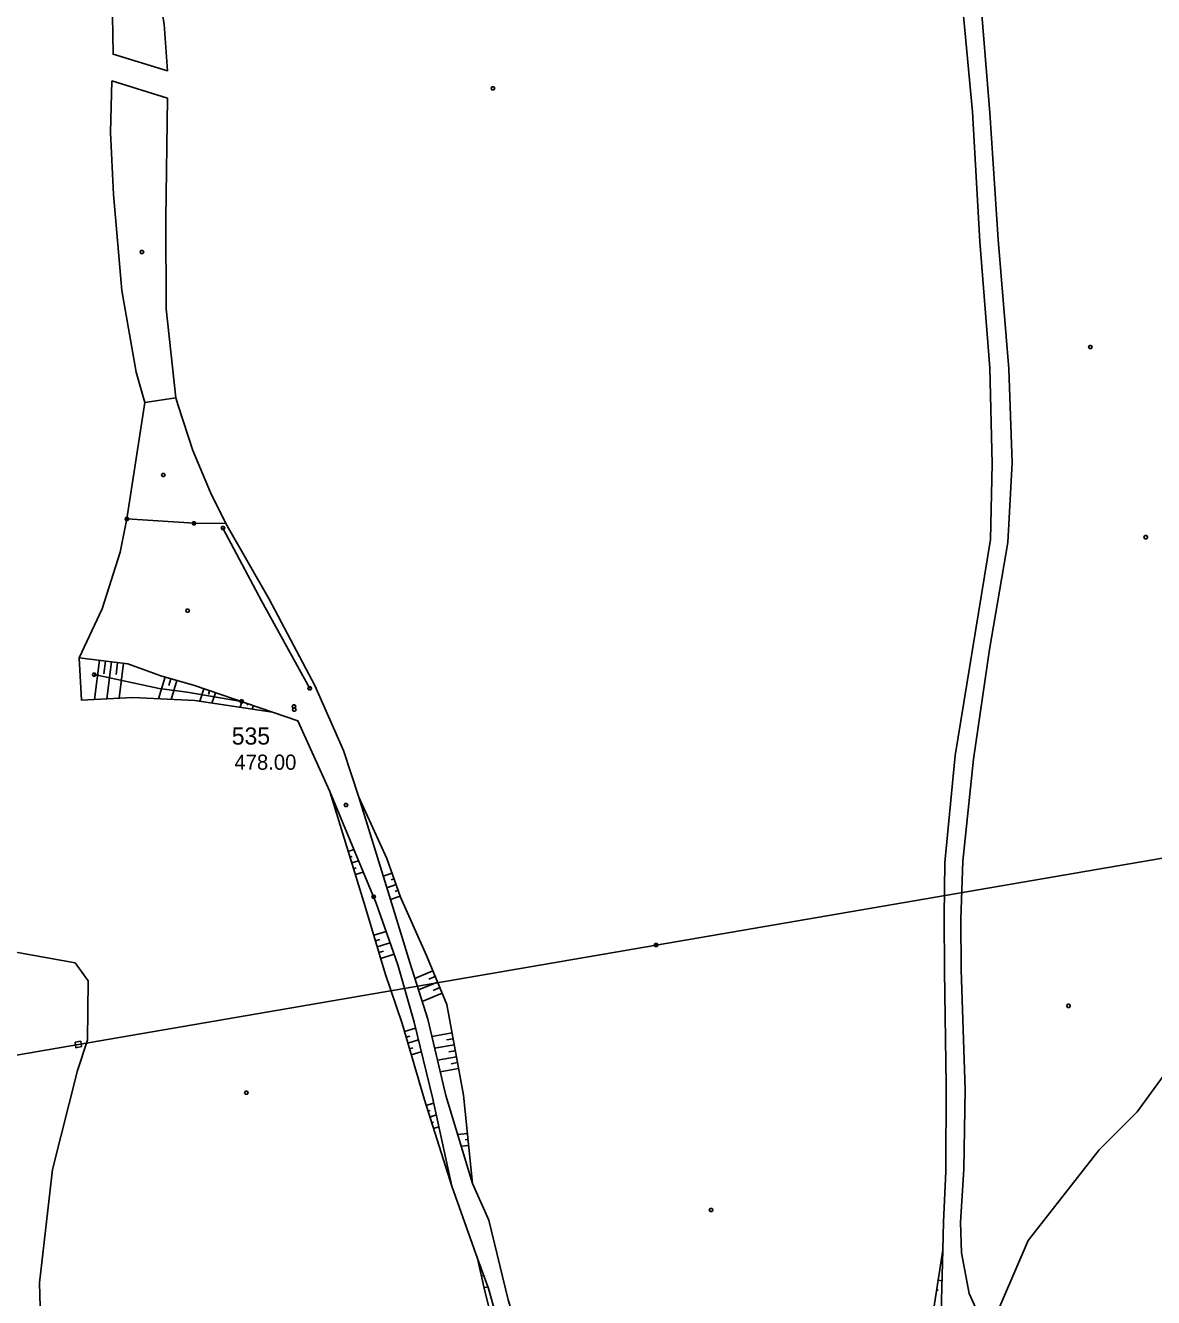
# Model space of a CAD drawing. Extents: x -664960 to -662754, y -993849 to -991145.
# Drawn here: x -663675.5 to -663452.1, y -992772.1 to -992520.3 of the extents above; entities that cross this region are included whole.
import ezdxf

# ---------------------------------------------------------------- set-up
doc = ezdxf.new("R2010")
doc.units = 0
for name, color, linetype in [('Vrstva 1', 7, 'Continuous'), ('Vrstva 13', 7, 'Continuous'), ('Vrstva 18', 7, 'Continuous'), ('Vrstva 27', 7, 'Continuous'), ('Vrstva 37', 7, 'Continuous'), ('Vrstva 57', 7, 'Continuous'), ('Vrstva 63', 7, 'Continuous'), ('Vrstva 8', 7, 'Continuous')]:
    doc.layers.add(name, color=color, linetype=linetype)

msp = doc.modelspace()

# ---------------------------------------------------------------- linework, layer by layer
at = {"layer": 'Vrstva 13'}
for points in [[(-663582.792, -992532.48), (-663582.612, -992532.78), (-663582.792, -992533.08), (-663583.152, -992533.08), (-663583.332, -992532.78), (-663583.152, -992532.48), (-663582.792, -992532.48)], [(-663652.3, -992564.888), (-663652.12, -992565.188), (-663652.3, -992565.488), (-663652.66, -992565.488), (-663652.84, -992565.188), (-663652.66, -992564.888), (-663652.3, -992564.888)], [(-663464.48, -992583.686), (-663464.3, -992583.986), (-663464.48, -992584.286), (-663464.84, -992584.286), (-663465.02, -992583.986), (-663464.84, -992583.686), (-663464.48, -992583.686)], [(-663648.07, -992609.011), (-663647.89, -992609.311), (-663648.07, -992609.611), (-663648.43, -992609.611), (-663648.61, -992609.311), (-663648.43, -992609.011), (-663648.07, -992609.011)], [(-663643.254, -992635.855), (-663643.074, -992636.155), (-663643.254, -992636.455), (-663643.614, -992636.455), (-663643.794, -992636.155), (-663643.614, -992635.855), (-663643.254, -992635.855)], [(-663611.867, -992674.338), (-663611.687, -992674.638), (-663611.867, -992674.938), (-663612.227, -992674.938), (-663612.407, -992674.638), (-663612.227, -992674.338), (-663611.867, -992674.338)], [(-663468.799, -992714.089), (-663468.619, -992714.389), (-663468.799, -992714.689), (-663469.159, -992714.689), (-663469.339, -992714.389), (-663469.159, -992714.089), (-663468.799, -992714.089)], [(-663631.602, -992731.282), (-663631.422, -992731.582), (-663631.602, -992731.882), (-663631.962, -992731.882), (-663632.142, -992731.582), (-663631.962, -992731.282), (-663631.602, -992731.282)], [(-663539.571, -992754.487), (-663539.391, -992754.787), (-663539.571, -992755.087), (-663539.931, -992755.087), (-663540.111, -992754.787), (-663539.931, -992754.487), (-663539.571, -992754.487)]]:
    msp.add_lwpolyline(points, dxfattribs=at)
at = {"layer": 'Vrstva 18'}
for points in [[(-663655.27, -992617.72), (-663655.09, -992618.02), (-663655.27, -992618.32), (-663655.63, -992618.32), (-663655.81, -992618.02), (-663655.63, -992617.72), (-663655.27, -992617.72)], [(-663641.97, -992618.57), (-663641.79, -992618.87), (-663641.97, -992619.17), (-663642.33, -992619.17), (-663642.51, -992618.87), (-663642.33, -992618.57), (-663641.97, -992618.57)], [(-663622.19, -992654.84), (-663622.01, -992655.14), (-663622.19, -992655.44), (-663622.55, -992655.44), (-663622.73, -992655.14), (-663622.55, -992654.84), (-663622.19, -992654.84)]]:
    msp.add_lwpolyline(points, dxfattribs=at)
at = {"layer": 'Vrstva 27'}
for points in [[(-663491.56, -992494.88), (-663490.88, -992498.85), (-663490.29, -992512.79), (-663488.02, -992537.43), (-663486.54, -992563.07), (-663484.58, -992588.12), (-663484.13, -992607.11), (-663484.46, -992622.09), (-663487.97, -992643.83), (-663491.41, -992664.81), (-663493.48, -992685.99), (-663493.6, -992696.61), (-663493.51, -992707.44), (-663493.24, -992730.03), (-663493.3, -992747.16)], [(-663490.38, -992757.18), (-663489.72, -992746.74), (-663489.45, -992730.95), (-663490.22, -992707.23), (-663490.33, -992697.21), (-663489.9, -992685.74), (-663487.82, -992665.56), (-663484.63, -992643.86), (-663480.98, -992622.66), (-663480.17, -992606.94), (-663480.82, -992588.29), (-663482.91, -992562.68), (-663484.55, -992537.62), (-663486.62, -992512.45), (-663487.48, -992498.66)], [(-663493.3, -992747.16), (-663493.74, -992757.17), (-663493.888, -992762.726), (-663494.182, -992775.159), (-663494.693, -992783.58), (-663494.915, -992797.656), (-663495.32, -992822.604), (-663494.616, -992861.372), (-663496.188, -992887.015)], [(-663490.38, -992757.18), (-663490.142, -992763.247), (-663488.658, -992771.319), (-663486.041, -992777.124)]]:
    msp.add_lwpolyline(points, dxfattribs=at)
at = {"layer": 'Vrstva 37'}
for points in [[(-663550.47, -992702.05), (-663550.29, -992702.35), (-663550.47, -992702.65), (-663550.83, -992702.65), (-663551.01, -992702.35), (-663550.83, -992702.05), (-663550.47, -992702.05)], [(-663665.67, -992721.57), (-663664.6, -992721.39), (-663664.42, -992722.47), (-663665.53, -992722.68), (-663665.67, -992721.57)]]:
    msp.add_lwpolyline(points, dxfattribs=at)
at = {"layer": 'Vrstva 57'}
for points in [[(-663665.051, -992722.016), (-663550.65, -992702.35), (-663440.01, -992683.39), (-663326.32, -992663.75), (-663217.09, -992644.97), (-663109.78, -992626.53), (-662986.28, -992605.36), (-662863.82, -992584.32), (-662754.25, -992565.49)], [(-663970.58, -992774.57), (-663947.81, -992770.51), (-663896.715, -992761.596), (-663794.75, -992744.35), (-663665.051, -992722.016)]]:
    msp.add_lwpolyline(points, dxfattribs=at)
at = {"layer": 'Vrstva 63'}
for p, q in [((-663660.864, -992645.988), (-663661.846, -992653.752)), ((-663659.673, -992646.138), (-663659.991, -992648.652)), ((-663658.483, -992646.289), (-663659.41, -992653.622)), ((-663657.292, -992646.439), (-663657.592, -992648.81)), ((-663656.102, -992646.59), (-663656.975, -992653.493)), ((-663647.893, -992649.295), (-663649.157, -992653.605)), ((-663646.741, -992649.632), (-663647.135, -992650.975)), ((-663645.59, -992649.97), (-663646.692, -992653.727)), ((-663640.195, -992651.641), (-663641.031, -992654.102)), ((-663639.059, -992652.027), (-663639.314, -992652.778)), ((-663637.922, -992652.414), (-663638.619, -992654.462)), ((-663632.667, -992654.201), (-663633.039, -992655.295)), ((-663631.531, -992654.587), (-663631.631, -992654.883)), ((-663630.395, -992654.973), (-663630.627, -992655.655)), ((-663611.62, -992683.813), (-663610.489, -992683.464)), ((-663611.266, -992684.96), (-663610.853, -992684.832)), ((-663610.912, -992686.106), (-663609.562, -992685.69)), ((-663610.558, -992687.253), (-663610.072, -992687.103)), ((-663610.204, -992688.4), (-663608.635, -992687.915)), ((-663602.924, -992688.126), (-663604.669, -992688.744)), ((-663602.123, -992690.388), (-663603.954, -992691.037)), ((-663602.523, -992689.257), (-663603.119, -992689.468)), ((-663601.321, -992692.65), (-663603.24, -992693.33)), ((-663601.722, -992691.519), (-663602.346, -992691.74)), ((-663606.561, -992700.389), (-663604.103, -992699.656)), ((-663606.218, -992701.539), (-663605.381, -992701.289)), ((-663605.875, -992702.689), (-663603.305, -992701.922)), ((-663605.532, -992703.839), (-663604.657, -992703.578)), ((-663605.189, -992704.989), (-663602.507, -992704.188)), ((-663594.863, -992707.466), (-663598.439, -992708.952)), ((-663594.402, -992708.574), (-663595.625, -992709.082)), ((-663593.942, -992709.682), (-663597.71, -992711.248)), ((-663593.482, -992710.79), (-663594.768, -992711.325)), ((-663593.021, -992711.899), (-663596.981, -992713.544)), ((-663600.494, -992719.453), (-663598.296, -992718.812)), ((-663600.158, -992720.605), (-663599.443, -992720.397)), ((-663599.822, -992721.757), (-663597.726, -992721.146)), ((-663591.065, -992719.728), (-663595.057, -992720.461)), ((-663590.848, -992720.909), (-663592.157, -992721.149)), ((-663599.486, -992722.909), (-663598.805, -992722.711)), ((-663599.15, -992724.061), (-663597.156, -992723.48)), ((-663590.631, -992722.089), (-663594.501, -992722.799)), ((-663590.415, -992723.269), (-663591.683, -992723.502)), ((-663590.198, -992724.45), (-663593.945, -992725.137)), ((-663589.982, -992725.63), (-663591.209, -992725.855)), ((-663589.765, -992726.81), (-663593.389, -992727.475)), ((-663596.187, -992734.114), (-663594.702, -992733.639)), ((-663595.822, -992735.257), (-663595.363, -992735.11)), ((-663595.457, -992736.4), (-663594.184, -992735.993)), ((-663595.092, -992737.543), (-663594.704, -992737.419)), ((-663594.727, -992738.686), (-663593.667, -992738.347)), ((-663588.024, -992739.653), (-663589.946, -992739.85)), ((-663587.901, -992740.846), (-663588.464, -992740.904)), ((-663587.779, -992742.04), (-663589.238, -992742.19)), ((-663591.09, -992750.07), (-663586.04, -992764.39)), ((-663585.795, -992765.497), (-663585.642, -992765.464)), ((-663585.535, -992766.669), (-663585.431, -992766.646)), ((-663585.276, -992767.841), (-663584.801, -992767.736)), ((-663585.016, -992769.012), (-663584.804, -992768.965)), ((-663494.813, -992768.67), (-663494.031, -992768.791)), ((-663584.757, -992770.184), (-663583.96, -992770.007)), ((-663495.12, -992770.646), (-663494.773, -992770.7))]:
    msp.add_line(p, q, dxfattribs=at)
for points in [[(-663666.65, -992441.9), (-663660.96, -992439.71), (-663658.84, -992459.72), (-663656.61, -992474.86), (-663653.61, -992490.73), (-663650.58, -992505.51), (-663648.09, -992520.05), (-663647.43, -992529.31), (-663658.19, -992526.04), (-663658.31, -992518.36), (-663658.27, -992513.04), (-663659.62, -992501.25), (-663662.18, -992486.36), (-663664.56, -992465.75), (-663666.58, -992451.8), (-663666.65, -992441.9)], [(-663658.41, -992531.33), (-663647.43, -992534.76), (-663647.72, -992558.59), (-663647.7, -992576.44), (-663645.73, -992594.04), (-663651.89, -992594.94), (-663653.63, -992588.97), (-663656.42, -992572.83), (-663658.08, -992553.77), (-663658.7, -992541.5), (-663658.41, -992531.33)], [(-663645.73, -992594.04), (-663645.32, -992595.57), (-663642.36, -992604.46), (-663638.88, -992612.76), (-663635.84, -992618.92), (-663642.15, -992618.87), (-663655.45, -992618.02), (-663651.89, -992594.94)], [(-663655.45, -992618.02), (-663656.81, -992624.59), (-663660.34, -992635.8), (-663664.88, -992645.48)], [(-663636.25, -992619.53), (-663636.07, -992619.83), (-663636.25, -992620.13), (-663636.61, -992620.13), (-663636.79, -992619.83), (-663636.61, -992619.53), (-663636.25, -992619.53)], [(-663636.43, -992619.83), (-663628.8, -992634.25), (-663619.23, -992651.55)], [(-663635.84, -992618.92), (-663627.3, -992633.89), (-663618.23, -992651), (-663612.54, -992663.83), (-663609.54, -992673.11)], [(-663453.5, -992621.32), (-663453.32, -992621.62), (-663453.5, -992621.92), (-663453.86, -992621.92), (-663454.04, -992621.62), (-663453.86, -992621.32), (-663453.5, -992621.32)], [(-663626.64, -992656.25), (-663641.98, -992653.96), (-663654.3, -992653.35), (-663664.43, -992653.89), (-663664.88, -992645.48)], [(-663664.88, -992645.48), (-663655.23, -992646.7), (-663648.76, -992649.04), (-663642.08, -992651), (-663626.64, -992656.25)], [(-663661.75, -992648.51), (-663661.57, -992648.81), (-663661.75, -992649.11), (-663662.11, -992649.11), (-663662.29, -992648.81), (-663662.11, -992648.51), (-663661.75, -992648.51)], [(-663632.73, -992654.13), (-663643.49, -992652.32), (-663649.07, -992651.55), (-663661.93, -992648.81)], [(-663619.05, -992651.25), (-663618.87, -992651.55), (-663619.05, -992651.85), (-663619.41, -992651.85), (-663619.59, -992651.55), (-663619.41, -992651.25), (-663619.05, -992651.25)], [(-663632.55, -992653.83), (-663632.37, -992654.13), (-663632.55, -992654.43), (-663632.91, -992654.43), (-663633.09, -992654.13), (-663632.91, -992653.83), (-663632.55, -992653.83)], [(-663626.64, -992656.25), (-663621.58, -992657.96), (-663615.27, -992671.99)], [(-663615.27, -992671.99), (-663608.25, -992694.73), (-663604.29, -992708), (-663600.95, -992717.89), (-663596.54, -992733.01), (-663591.09, -992750.07)], [(-663591.09, -992750.07), (-663594.95, -992732.51), (-663598.59, -992717.61), (-663601.77, -992706.28), (-663606.07, -992694.07), (-663615.27, -992671.99)], [(-663609.54, -992673.11), (-663603.95, -992685.23), (-663601.24, -992692.88), (-663596.12, -992704.44), (-663592.09, -992714.14), (-663588.8, -992732.07), (-663587.01, -992749.55)], [(-663587.01, -992749.55), (-663592.28, -992732.14), (-663595.87, -992717.04), (-663599.44, -992705.8), (-663603.24, -992693.33), (-663609.54, -992673.11)], [(-663717.47, -992690.93), (-663688.56, -992701.81), (-663665.72, -992705.89), (-663663.12, -992709.42), (-663663.27, -992721.2), (-663665.23, -992727.21), (-663670.19, -992746.8), (-663672.76, -992769.22), (-663672.43, -992781.22), (-663666.45, -992787.76)], [(-663606.4, -992692.51), (-663606.22, -992692.81), (-663606.4, -992693.11), (-663606.76, -992693.11), (-663606.94, -992692.81), (-663606.76, -992692.51), (-663606.4, -992692.51)], [(-663484.479, -992778.312), (-663476.949, -992760.827), (-663462.91, -992742.863), (-663455.403, -992735.348), (-663447.365, -992724.436), (-663443.35, -992711.5)], [(-663587.01, -992749.55), (-663583.75, -992756.81), (-663579.92, -992772.55), (-663573.91, -992792.31)], [(-663556.8, -992863.63), (-663560.13, -992859.1), (-663563.04, -992852.55), (-663569.82, -992838.63), (-663572.12, -992831.69), (-663575.48, -992807.85), (-663578.87, -992793.35), (-663584.66, -992770.62), (-663586.04, -992764.39), (-663583.84, -992770.33), (-663577.42, -992793.21), (-663574.33, -992807.61), (-663571.21, -992831.41), (-663568.69, -992837.99), (-663562.01, -992852.26), (-663558.97, -992858.43), (-663556.8, -992863.63)], [(-663493.888, -992762.726), (-663496.142, -992777.214), (-663496.083, -992797.466), (-663496.579, -992822.93), (-663495.652, -992861.485), (-663496.993, -992880.388), (-663496.188, -992887.015)]]:
    msp.add_lwpolyline(points, dxfattribs=at)
at = {"layer": 'Vrstva 8'}
msp.add_lwpolyline([(-663622.14, -992655.44), (-663621.96, -992655.74), (-663622.14, -992656.04), (-663622.5, -992656.04), (-663622.68, -992655.74), (-663622.5, -992655.44), (-663622.14, -992655.44)], dxfattribs=at)

# ---------------------------------------------------------------- texts
at = {"layer": 'Vrstva 1'}
msp.add_text('535', height=3.4, dxfattribs=at).set_placement((-663634.679, -992662.682))
at = {"layer": 'Vrstva 63'}
msp.add_text('478.00', height=3, dxfattribs=at).set_placement((-663634.155, -992667.662))

doc.saveas('drawing.dxf')
